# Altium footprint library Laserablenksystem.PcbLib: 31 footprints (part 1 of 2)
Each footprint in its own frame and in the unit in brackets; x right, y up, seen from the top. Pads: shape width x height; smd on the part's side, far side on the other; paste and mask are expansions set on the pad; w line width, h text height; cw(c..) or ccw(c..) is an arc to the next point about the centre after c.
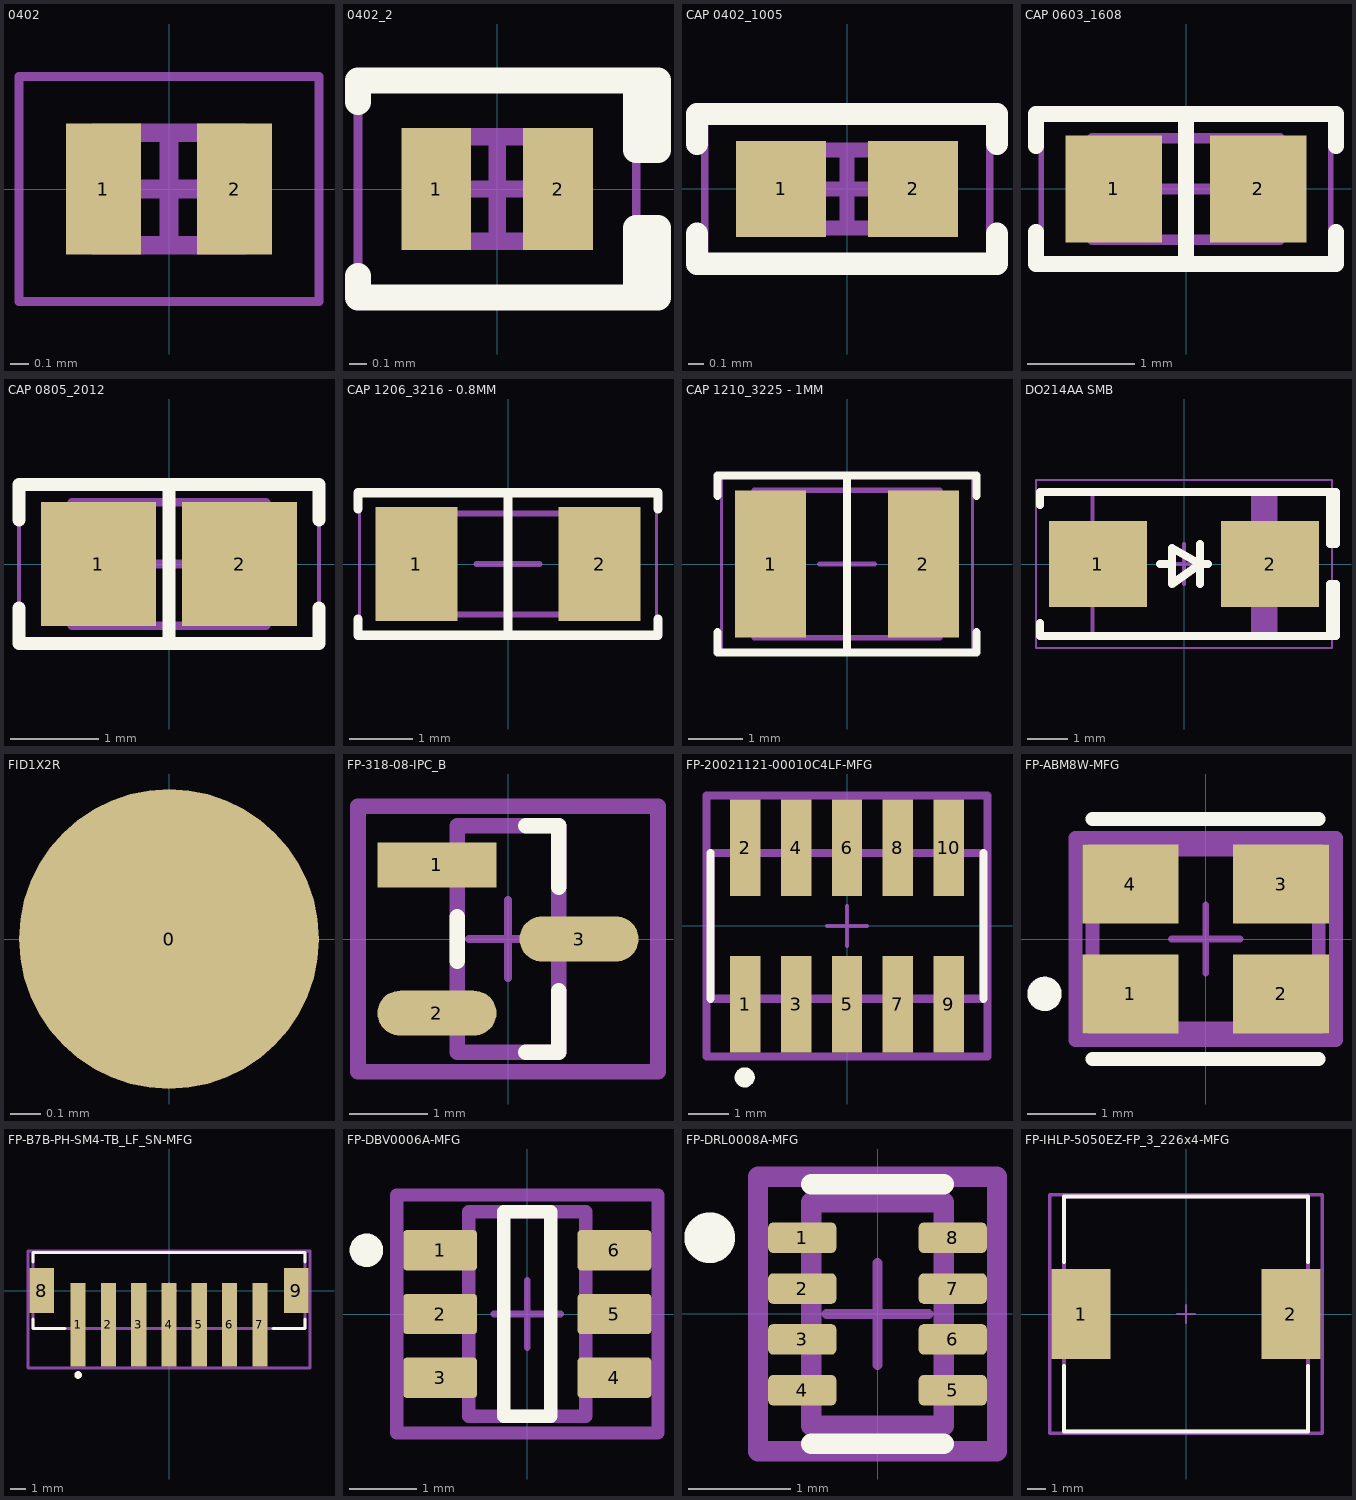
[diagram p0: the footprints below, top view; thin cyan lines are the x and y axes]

## 0402 [mm] "SODFL, 2-Leads, Body 0.675x1.075mm, IPC Medium Density"
height 0.4
pads (2):
  rect 0.4x0.7 smd: 1(-0.35,0) 2(0.35,0)
Mechanical 13:
  lines w0.1: -0.4,-0.3 0.4,-0.3 0.4,0.3 -0.4,0.3 -0.4,-0.3
Mechanical 15:
  lines w0.05: -0.8,-0.6 0.8,-0.6 0.8,0.6 -0.8,0.6 -0.8,-0.6
  lines w0.1: -0.25,0 0.25,0 ; 0,-0.25 0,0.25
3D body "DIODE - 0402.step": height 0.45, standoff 0, extent -0.505,-0.305 0.505,0.305

## 0402_2 [mm]
pads (2):
  rect 0.4x0.7 smd: 1(-0.35,0) 2(0.35,0)
Top Overlay:
  lines w0.15: -0.8,-0.5 -0.8,-0.625 0.8,-0.625 ; -0.8,0.5 -0.8,0.625 0.8,0.625 ; 0.8,-0.625 0.8,-0.225 0.925,-0.225 0.925,-0.625 0.8,-0.625 ; 0.8,0.625 0.925,0.625 0.925,0.225 0.8,0.225 0.8,0.625
Mechanical 13:
  lines w0.1: -0.4,-0.3 -0.4,0.3 0.4,0.3 0.4,-0.3 -0.4,-0.3
Mechanical 15:
  lines w0.05: -0.8,-0.6 -0.8,0.6 0.8,0.6 0.8,-0.6 -0.8,-0.6
  lines w0.1: -0.25,0 0.25,0 ; 0,-0.25 0,0.25
3D body "DIODE - 0402.step": height 0.45, standoff 0, extent -0.505,-0.305 0.505,0.305

## CAP 0402_1005 [mm] "Chip Capacitor, 2-Leads, Body 1.02x0.51mm, IPC Medium Density"
height 0.52
pads (2):
  rect 0.6x0.64 smd: 1(-0.44,0) 2(0.44,0)
Top Overlay:
  lines w0.15: -1,-0.3 -1,-0.5 1,-0.5 1,-0.3 ; -1,0.3 -1,0.5 1,0.5 1,0.3
Mechanical 13:
  lines w0.1: -0.515,-0.26 -0.515,0.26 0.515,0.26 0.515,-0.26 -0.515,-0.26
Mechanical 15:
  lines w0.05: -0.95,-0.5 -0.95,0.5 0.95,0.5 0.95,-0.5 -0.95,-0.5
  lines w0.1: -0.26,0 0.26,0 ; 0,-0.26 0,0.26
3D body "0402 cap.STEP": height 0.52, standoff 0, extent -0.5,-0.262 0.5,0.262

## CAP 0603_1608 [mm] "Chip Capacitor, 2-Leads, Body 1.60x0.80mm, IPC Medium Density"
height 0.89
pads (2):
  rect 0.9x1 smd: 1(-0.675,0) 2(0.675,0)
Top Overlay:
  lines w0.15: -1.4,-0.4 -1.4,-0.7 1.4,-0.7 1.4,-0.4 ; -1.4,0.4 -1.4,0.7 1.4,0.7 1.4,0.4 ; 0,-0.7 0,0.7
Mechanical 13:
  lines w0.1: -0.875,-0.475 0.875,-0.475 0.875,0.475 -0.875,0.475 -0.875,-0.475
Mechanical 15:
  lines w0.05: -1.35,-0.75 1.35,-0.75 1.35,0.75 -1.35,0.75 -1.35,-0.75
  lines w0.1: -0.475,0 0.475,0 ; 0,-0.475 0,0.475
3D body "0603 cap.STEP": height 0.82, standoff 0, extent -0.8,-0.412 0.8,0.412

## CAP 0805_2012 [mm] "Chip Capacitor, 2-Leads, Body 2.00x1.20mm, IPC Medium Density"
height 1.15
pads (2):
  rect 1.3x1.4 smd: 1(-0.8,0) 2(0.8,0)
Top Overlay:
  lines w0.15: -1.7,-0.5 -1.7,-0.9 1.7,-0.9 1.7,-0.5 ; -1.7,0.5 -1.7,0.9 1.7,0.9 1.7,0.5 ; 0,-0.9 0,0.9
Mechanical 13:
  lines w0.1: -1.1,-0.7 1.1,-0.7 1.1,0.7 -1.1,0.7 -1.1,-0.7
Mechanical 15:
  lines w0.05: -1.7,-0.95 1.7,-0.95 1.7,0.95 -1.7,0.95 -1.7,-0.95
  lines w0.1: -0.5,0 0.5,0 ; 0,-0.5 0,0.5
3D body "0805 cap.STEP": height 1.26, standoff -0.02, extent -1,-0.637 1,0.637

## CAP 1206_3216 - 0.8MM [mm] "Chip Capacitor, 2-Leads, Body 3.25x1.60mm, IPC Medium Density"
height 0.8
pads (2):
  rect 1.3x1.8 smd: 1(-1.45,0) 2(1.45,0)
Top Overlay:
  lines w0.15: -2.375,-0.875 -2.375,-1.125 2.375,-1.125 2.375,-0.875 ; -2.375,0.875 -2.375,1.125 2.375,1.125 2.375,0.875 ; 0,-1.125 0,1.125
Mechanical 13:
  lines w0.1: -1.6,-0.8 1.6,-0.8 1.6,0.8 -1.6,0.8 -1.6,-0.8
Mechanical 15:
  lines w0.05: -2.35,-1.15 2.35,-1.15 2.35,1.15 -2.35,1.15 -2.35,-1.15
  lines w0.1: -0.5,0 0.5,0 ; 0,-0.5 0,0.5
3D body "CAP 1206-0.8mm.STEP": height 0.8, standoff 0, extent -1.6,-0.8 1.6,0.8

## CAP 1210_3225 - 1MM [mm] "Chip Capacitor, 2-Leads, Body 3.20x2.50mm, IPC Medium Density"
height 1
pads (2):
  rect 1.3x2.7 smd: 1(-1.4,0) 2(1.4,0)
Top Overlay:
  lines w0.15: -2.375,-1.25 -2.375,-1.625 2.375,-1.625 2.375,-1.25 ; -2.375,1.25 -2.375,1.625 2.375,1.625 2.375,1.25 ; 0,-1.625 0,1.625
Mechanical 13:
  lines w0.1: -1.7,-1.35 -1.7,1.35 1.7,1.35 1.7,-1.35 -1.7,-1.35
Mechanical 15:
  lines w0.05: -2.3,-1.6 -2.3,1.6 2.3,1.6 2.3,-1.6 -2.3,-1.6
  lines w0.1: -0.5,0 0.5,0 ; 0,-0.5 0,0.5
3D body "CAP 1210-1mm.STEP": height 1, standoff 0, extent -1.6,-1.25 1.6,1.25

## DO214AA SMB [mm] "Molded Diode, 2-Leads, Body 4.31x3.62mm, IPC Medium Density"
height 2.44
pads (2):
  rect 2.45x2.15 smd: 1(-2.15,0) 2(2.15,0)
Top Overlay:
  lines w0.2: -3.6,-1.475 -3.6,-1.8 3.8,-1.8 3.8,-0.5 3.65,-0.5 3.65,-1.8 ; -3.6,1.475 -3.6,1.8 3.8,1.8 3.8,0.5 3.65,0.5 3.65,1.8 ; -0.6,0 -0.3,0 ; 0.4,-0.5 0.4,0.5 ; 0.6,0 0.4,0 ; 0.4,0 -0.3,0.4 -0.3,-0.5 0.4,0
Mechanical 13:
  rectangle: 1.671,-1.8 2.285,1.8
  lines w0.1: -2.285,-1.8 2.285,-1.8 2.285,1.8 -2.285,1.8 -2.285,-1.8
Mechanical 15:
  lines w0.05: -3.7,-2.1 3.7,-2.1 3.7,2.1 -3.7,2.1 -3.7,-2.1
  lines w0.1: -0.5,0 0.5,0 ; 0,-0.5 0,0.5
3D body "SMB.STEP": height 2.4, standoff 0, extent -2.6,-1.8 2.6,1.8

## FID1X2R [mm] "Fiducial - Round 1x2mm"
pads (1):
  round 1 smd paste+0 mask+0.5: 0(0,0)
Top Designator:
  text ".Designator" at -1.27,-0.127 h0.6

## FP-318-08-IPC_B [mm]
pads (3):
  rect 1.524x0.578 smd paste+0 mask+0: 1(-0.91,0.95)
  rrect100% 1.524x0.578 smd paste+0 mask+0: 2(-0.91,-0.95) 3(0.91,0)
Top Overlay:
  lines w0.2: -0.65,-0.286 -0.65,0.286 ; 0.227,-1.45 0.65,-1.45 0.65,-0.664 ; 0.227,1.45 0.65,1.45 0.65,0.664
Top 3D Body:
  lines w0.2: -0.65,-1.45 0.65,-1.45 0.65,1.45 -0.65,1.45 -0.65,-1.45
Top Courtyard:
  lines w0.2: -1.922,-1.7 1.922,-1.7 1.922,1.7 -1.922,1.7 -1.922,-1.7
Top Assembly:
  lines w0.2: -1.922,-1.7 1.922,-1.7 1.922,1.7 -1.922,1.7 -1.922,-1.7
  text ".Designator" at 0,-0.001 h1
Top Component Center:
  lines w0.1: -0.5,0 0.5,0 ; 0,-0.5 0,0.5
3D body "IC_ON_Semiconductor_NUD3112LT1G_eec.STEP": height 0.25, standoff 0, extent -1.922,-1.7 1.922,1.7

## FP-20021121-00010C4LF-MFG [mm]
pads (10):
  rect 0.76x2.4 smd paste+0 mask+0: 1(-2.54,-1.95) 2(-2.54,1.95) 3(-1.27,-1.95) 4(-1.27,1.95) 5(0,-1.95) 6(0,1.95) 7(1.27,-1.95) 8(1.27,1.95) 9(2.54,-1.95) 10(2.54,1.95)
Top Overlay:
  circle w0.25: c-2.55,-3.775 r0.125
  lines w0.2: -3.4,-1.815 -3.4,1.815 ; 3.4,-1.815 3.4,1.815
Top 3D Body:
  lines w0.2: -3.4,-1.815 -3.4,1.815 3.4,1.815 3.4,-1.815 -3.4,-1.815
Top Courtyard:
  lines w0.2: -3.5,-3.25 -3.5,3.25 3.5,3.25 3.5,-3.25 -3.5,-3.25
Top Assembly:
  lines w0.2: -3.5,-3.25 -3.5,3.25 3.5,3.25 3.5,-3.25 -3.5,-3.25
  text ".Designator" at 0,-0.001 h1
Top Component Center:
  lines w0.1: -0.5,0 0.5,0 ; 0,-0.5 0,0.5
3D body "Conn_Amphenol_ICC_-_FCI_20021121-00010C4LF_eec.STEP": height 0.25, standoff 0, extent -3.5,-3.25 3.5,3.25

## FP-ABM8W-MFG [mm]
pads (4):
  rect 1.4x1.15 smd paste+0 mask+0: 1(-1.1,-0.8) 2(1.1,-0.8) 3(1.1,0.8) 4(-1.1,0.8)
Top Overlay:
  circle w0.25: c-2.35,-0.8 r0.125
  lines w0.2: -1.65,-1.75 1.65,-1.75 ; -1.65,1.75 1.65,1.75
Top 3D Body:
  lines w0.2: -1.65,-1.3 -1.65,1.3 1.65,1.3 1.65,-1.3 -1.65,-1.3
Top Courtyard:
  lines w0.2: -1.9,-1.475 -1.9,1.475 1.9,1.475 1.9,-1.475 -1.9,-1.475
Top Assembly:
  lines w0.2: -1.9,-1.475 -1.9,1.475 1.9,1.475 1.9,-1.475 -1.9,-1.475
  text ".Designator" at 0,0.188 h1
Top Component Center:
  lines w0.1: -0.5,0 0.5,0 ; 0,-0.5 0,0.5
3D body "Crys_Abracon_ABM8W-12_0000MHZ-4-B1U-T3_eec.STEP": height 0.25, standoff 0, extent -1.9,-1.475 1.9,1.475

## FP-B7B-PH-SM4-TB_LF_SN-MFG [mm]
pads (9):
  rect 1x5.5 smd paste+0 mask+0: 1(-6,-2.25) 2(-4,-2.25) 3(-2,-2.25) 4(0,-2.25) 5(2,-2.25) 6(4,-2.25) 7(6,-2.25)
  rect 1.6x3 smd paste+0 mask+0: 8(-8.4,0) 9(8.4,0)
Top Overlay:
  circle w0.25: c-6,-5.575 r0.125
  lines w0.2: -8.975,-1.875 -8.975,-2.5 -6.875,-2.5 ; -8.975,1.875 -8.975,2.5 8.975,2.5 8.975,1.875 ; 6.875,-2.5 8.975,-2.5 8.975,-1.875
Top 3D Body:
  lines w0.2: -8.975,-2.5 8.975,-2.5 8.975,2.5 -8.975,2.5 -8.975,-2.5
Top Courtyard:
  lines w0.2: -9.3,-5.1 9.3,-5.1 9.3,2.6 -9.3,2.6 -9.3,-5.1
Top Assembly:
  lines w0.2: -9.3,-5.1 9.3,-5.1 9.3,2.6 -9.3,2.6 -9.3,-5.1
  text ".Designator" at 0,-1.251 h1
Top Component Center:
  lines w0.1: -0.5,0 0.5,0 ; 0,-0.5 0,0.5
3D body "Conn_JST_B7B-PH-SM4-TB_LF_SN_eec.STEP": height 0.25, standoff 0, extent -9.3,-5.1 9.3,2.6

## FP-DBV0006A-MFG [mm]
pads (6):
  rrect17% 1.1x0.6 smd paste+0 mask+0: 1(-1.3,0.95) 2(-1.3,0) 3(-1.3,-0.95) 4(1.3,-0.95) 5(1.3,0) 6(1.3,0.95)
Top Overlay:
  circle w0.25: c-2.4,0.95 r0.125
  lines w0.2: -0.35,-1.525 0.35,-1.525 0.35,1.525 -0.35,1.525 -0.35,-1.525
Top 3D Body:
  lines w0.2: -0.875,-1.525 0.875,-1.525 0.875,1.525 -0.875,1.525 -0.875,-1.525
Top Courtyard:
  lines w0.2: -1.95,-1.775 1.95,-1.775 1.95,1.775 -1.95,1.775 -1.95,-1.775
Top Assembly:
  lines w0.2: -1.95,-1.775 1.95,-1.775 1.95,1.775 -1.95,1.775 -1.95,-1.775
  text ".Designator" at 0,0.188 h1
Top Component Center:
  lines w0.1: -0.5,0 0.5,0 ; 0,-0.5 0,0.5
3D body "IC_Texas_Instruments_LM74700QDBVRQ1_eec.STEP": height 0.25, standoff 0, extent -1.95,-1.775 1.95,1.775

## FP-DRL0008A-MFG [mm]
pads (8):
  rrect33% 0.67x0.3 smd paste+0 mask+0: 1(-0.74,0.75) 2(-0.74,0.25) 3(-0.74,-0.25) 4(-0.74,-0.75) 5(0.74,-0.75) 6(0.74,-0.25) 7(0.74,0.25) 8(0.74,0.75)
Top Overlay:
  circle w0.25: c-1.65,0.75 r0.125
  lines w0.2: -0.65,-1.275 0.65,-1.275 ; -0.65,1.275 0.65,1.275
Top 3D Body:
  lines w0.2: -0.65,-1.1 -0.65,1.1 0.65,1.1 0.65,-1.1 -0.65,-1.1
Top Courtyard:
  lines w0.2: -1.175,-1.35 -1.175,1.35 1.175,1.35 1.175,-1.35 -1.175,-1.35
Top Assembly:
  lines w0.2: -1.175,-1.35 -1.175,1.35 1.175,1.35 1.175,-1.35 -1.175,-1.35
  text ".Designator" at 0,0.188 h1
Top Component Center:
  lines w0.1: -0.5,0 0.5,0 ; 0,-0.5 0,0.5
3D body "IC_Texas_Instruments_TPS628501QDRLRQ1_eec.STEP": height 0.25, standoff 0, extent -1.175,-1.35 1.175,1.35

## FP-IHLP-5050EZ-FP_3_226x4-MFG [mil]
pads (2):
  rect 127.01x195 smd paste+0 mask+0: 1(-226.5,0) 2(226.5,0)
Top Overlay:
  lines w7.87: -263.5,-112.26 -263.5,-253.94 263.5,-253.94 263.5,-112.26 ; -263.5,112.26 -263.5,253.94 263.5,253.94 263.5,112.26
Top 3D Body:
  lines w7.87: -263.5,-253.94 263.5,-253.94 263.5,253.94 -263.5,253.94 -263.5,-253.94
Top Courtyard:
  lines w7.87: -293.94,-257.87 293.94,-257.87 293.94,257.87 -293.94,257.87 -293.94,-257.87
Top Assembly:
  lines w7.87: -293.94,-257.87 293.94,-257.87 293.94,257.87 -293.94,257.87 -293.94,-257.87
  text ".Designator" at 0,7.39 h39.37
Top Component Center:
  lines w3.94: -19.68,0 19.68,0 ; 0,-19.68 0,19.68
3D body "Ind_Vishay_IHLP5050EZER5R6M5A_eec.STEP": height 10, standoff 0, extent -293.94,-257.87 293.94,257.87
